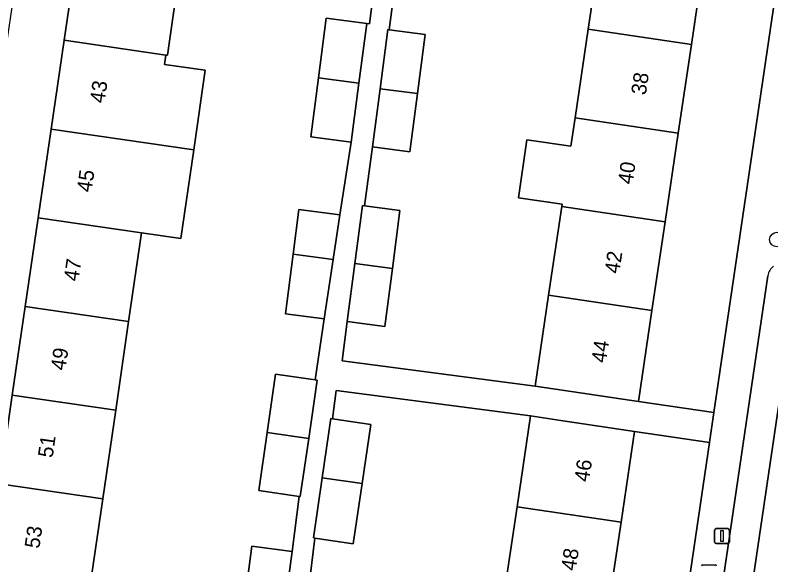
# Model space of a CAD drawing. Extents: x 163683 to 164494, y 382709 to 383872.
# Drawn here: x 163863.1 to 163913.7, y 383038.7 to 383075.5 of the extents above; entities that cross this region are included whole.
import ezdxf

# ---------------------------------------------------------------- set-up
doc = ezdxf.new("R2010")
doc.units = 0
for name, color, linetype in [('IMGEO_Boom', 7, 'Continuous'), ('IMGEO_Brandkraan', 7, 'Continuous'), ('IMGEO_Erf', 7, 'Continuous'), ('IMGEO_Lichtmast', 7, 'Continuous'), ('IMGEO_Pand', 7, 'Continuous'), ('IMGEO_Pand_nummerreeks', 7, 'Continuous'), ('IMGEO_Parkeervlak_open', 7, 'Continuous'), ('IMGEO_Rijbaan_lokaal_open', 7, 'Continuous'), ('IMGEO_Voetpad_open', 7, 'Continuous')]:
    doc.layers.add(name, color=color, linetype=linetype)

msp = doc.modelspace()

# ---------------------------------------------------------------- linework, layer by layer
at = {"layer": 'IMGEO_Boom'}
msp.add_circle((163914.106, 383060.495), 0.489, dxfattribs=at)
at = {"layer": 'IMGEO_Brandkraan'}
msp.add_line((163909.146, 383038.717), (163909.998, 383038.717), dxfattribs=at)
msp.add_lwpolyline([(163909.146, 383038.717), (163909.998, 383038.717)], dxfattribs=at)
for centre, start, end in [((163909.148, 383038.641), 91.552, 178.448), ((163909.148, 383038.641), 91.552, 178.448), ((163909.996, 383038.641), 1.552, 88.448), ((163909.996, 383038.641), 1.552, 88.448)]:
    msp.add_arc(centre, 0.0765, start, end, dxfattribs=at)
at = {"layer": 'IMGEO_Erf'}
for points in [[(163866.413, 383073.834), (163867.282, 383079.771), (163868.151, 383085.709), (163869.02, 383091.646), (163869.889, 383097.585), (163870.78, 383103.672), (163867.085, 383104.221), (163858.422, 383045.96), (163856.474, 383032.686), (163860.309, 383032.123), (163861.199, 383038.207), (163862.068, 383044.144), (163862.937, 383050.083), (163863.806, 383056.02), (163864.675, 383061.958), (163865.544, 383067.895)], [(163916.099, 383091.164), (163916.899, 383096.737), (163911.94, 383097.474), (163911.035, 383091.386), (163910.153, 383085.446), (163909.27, 383079.505), (163908.387, 383073.564), (163907.504, 383067.623), (163906.621, 383061.683), (163905.738, 383055.742), (163904.834, 383049.656), (163909.88, 383048.913)], [(163909.586, 383046.915), (163904.582, 383047.652), (163903.678, 383041.571), (163902.797, 383035.64), (163901.916, 383029.709), (163901.034, 383023.778), (163900.153, 383017.848), (163899.272, 383011.917), (163898.39, 383005.986), (163897.509, 383000.055), (163896.632, 382994.123), (163895.755, 382988.191), (163894.879, 382982.26), (163893.979, 382976.173), (163896.128, 382975.857), (163899.064, 382975.425)]]:
    msp.add_lwpolyline(points, close=True, dxfattribs=at)
for points in [[(163888.687, 383078.646), (163888.164, 383074.536), (163890.562, 383074.223), (163890.045, 383070.264), (163889.538, 383066.379), (163887.055, 383066.703), (163886.52, 383062.754), (163888.883, 383062.445), (163888.376, 383058.563), (163887.87, 383054.681), (163885.359, 383055.009), (163885.015, 383052.368), (163897.928, 383050.682), (163898.832, 383056.768), (163899.715, 383062.709), (163899.737, 383062.857), (163896.804, 383063.293), (163897.382, 383067.182), (163900.315, 383066.746), (163900.598, 383068.65), (163901.48, 383074.591), (163902.363, 383080.532)], [(163874.184, 383078.767), (163873.319, 383072.829), (163873.22, 383072.843), (163873.13, 383072.225), (163875.853, 383071.828), (163875.079, 383066.508), (163874.215, 383060.57), (163871.59, 383060.952), (163870.725, 383055.013), (163869.861, 383049.075), (163868.996, 383043.136), (163868.132, 383037.198)], [(163878.407, 383035.703), (163878.964, 383039.975), (163881.662, 383039.623), (163882.143, 383043.302), (163879.428, 383043.697), (163879.995, 383047.591), (163880.562, 383051.486), (163883.206, 383051.101), (163883.813, 383055.193), (163881.215, 383055.532), (163881.735, 383059.52), (163882.126, 383062.512), (163884.869, 383062.154), (163885.625, 383067.019), (163882.912, 383067.374), (163883.427, 383071.317), (163883.949, 383075.319), (163886.662, 383074.965), (163886.836, 383074.94), (163887.315, 383078.614)], [(163895.843, 383036.673), (163896.725, 383042.604), (163897.628, 383048.685), (163884.617, 383050.383), (163884.36, 383048.495), (163886.923, 383048.122), (163886.346, 383044.155), (163885.761, 383040.135), (163883.189, 383040.509), (163882.753, 383037.034)]]:
    msp.add_lwpolyline(points, dxfattribs=at)
at = {"layer": 'IMGEO_Lichtmast'}
for p, q in [((163909.94, 383040.249), (163909.94, 383041.049)), ((163909.94, 383041.049), (163909.94, 383040.249)), ((163910.04, 383041.149), (163910.83, 383041.149)), ((163910.83, 383041.149), (163910.04, 383041.149)), ((163910.93, 383041.049), (163910.93, 383040.249)), ((163910.93, 383040.249), (163910.93, 383041.049)), ((163910.83, 383040.149), (163910.04, 383040.149)), ((163910.04, 383040.149), (163910.83, 383040.149))]:
    msp.add_line(p, q, dxfattribs=at)
msp.add_lwpolyline([(163910.36, 383041.024), (163910.51, 383041.024), (163910.51, 383040.274), (163910.36, 383040.274), (163910.36, 383041.024)], dxfattribs=at)
for centre, start, end in [((163910.04, 383041.049), 90, 180), ((163910.04, 383041.049), 90, 180), ((163910.83, 383041.049), 0, 90), ((163910.83, 383041.049), 360, 90), ((163910.04, 383040.249), 180, 270), ((163910.04, 383040.249), 180, 270), ((163910.83, 383040.249), 270, 0), ((163910.83, 383040.249), 270, 0)]:
    msp.add_arc(centre, 0.1, start, end, dxfattribs=at)
at = {"layer": 'IMGEO_Pand'}
for points in [[(163908.387, 383073.564), (163909.27, 383079.505), (163902.363, 383080.532), (163901.48, 383074.591)], [(163874.184, 383078.767), (163867.282, 383079.771), (163866.413, 383073.834), (163873.22, 383072.843), (163873.319, 383072.829)], [(163886.662, 383074.965), (163883.949, 383075.319), (163883.427, 383071.317), (163886.139, 383070.963)], [(163888.164, 383074.536), (163888.079, 383074.547), (163887.562, 383070.588), (163890.045, 383070.264), (163890.562, 383074.223)], [(163900.598, 383068.65), (163907.504, 383067.623), (163908.387, 383073.564), (163901.48, 383074.591)], [(163873.22, 383072.843), (163866.413, 383073.834), (163865.544, 383067.895), (163875.079, 383066.508), (163875.853, 383071.828), (163873.13, 383072.225)], [(163886.139, 383070.963), (163883.427, 383071.317), (163882.912, 383067.374), (163885.625, 383067.019)], [(163890.045, 383070.264), (163887.562, 383070.588), (163887.055, 383066.703), (163889.538, 383066.379)], [(163907.504, 383067.623), (163900.598, 383068.65), (163900.315, 383066.746), (163897.382, 383067.182), (163896.804, 383063.293), (163899.737, 383062.857), (163899.715, 383062.709), (163906.621, 383061.683)], [(163871.59, 383060.952), (163874.215, 383060.57), (163875.079, 383066.508), (163865.544, 383067.895), (163864.675, 383061.958)], [(163886.52, 383062.754), (163886.372, 383062.773), (163885.865, 383058.891), (163888.376, 383058.563), (163888.883, 383062.445)], [(163905.738, 383055.742), (163906.621, 383061.683), (163899.715, 383062.709), (163898.832, 383056.768)], [(163884.869, 383062.154), (163882.126, 383062.512), (163881.735, 383059.52), (163884.416, 383059.17)], [(163871.59, 383060.952), (163864.675, 383061.958), (163863.806, 383056.02), (163870.725, 383055.013)], [(163884.416, 383059.17), (163881.735, 383059.52), (163881.215, 383055.532), (163883.813, 383055.193)], [(163888.376, 383058.563), (163885.865, 383058.891), (163885.359, 383055.009), (163887.87, 383054.681)], [(163905.738, 383055.742), (163898.832, 383056.768), (163897.928, 383050.682), (163899.889, 383050.391), (163904.834, 383049.656)], [(163869.861, 383049.075), (163870.725, 383055.013), (163863.806, 383056.02), (163862.937, 383050.083)], [(163883.206, 383051.101), (163880.562, 383051.486), (163879.995, 383047.591), (163882.779, 383047.186), (163883.345, 383051.081)], [(163862.068, 383044.144), (163868.996, 383043.136), (163869.861, 383049.075), (163862.937, 383050.083)], [(163884.36, 383048.495), (163884.255, 383048.51), (163883.677, 383044.543), (163886.346, 383044.155), (163886.923, 383048.122)], [(163896.725, 383042.604), (163903.678, 383041.571), (163904.582, 383047.652), (163899.637, 383048.387), (163897.628, 383048.685)], [(163882.779, 383047.186), (163879.995, 383047.591), (163879.428, 383043.697), (163882.143, 383043.302), (163882.212, 383043.292)], [(163886.346, 383044.155), (163883.677, 383044.543), (163883.093, 383040.523), (163883.189, 383040.509), (163885.761, 383040.135)], [(163868.132, 383037.198), (163868.996, 383043.136), (163862.068, 383044.144), (163861.199, 383038.207)], [(163902.797, 383035.64), (163903.678, 383041.571), (163896.725, 383042.604), (163895.843, 383036.673)], [(163881.099, 383035.311), (163881.662, 383039.623), (163878.964, 383039.975), (163878.407, 383035.703)]]:
    msp.add_lwpolyline(points, close=True, dxfattribs=at)
at = {"layer": 'IMGEO_Parkeervlak_open'}
for points in [[(163906.683, 382998.169), (163915.86, 383060.494)], [(163913.496, 383058.068), (163905.193, 383001.625)]]:
    msp.add_lwpolyline(points, dxfattribs=at)
msp.add_arc((163914.447, 383057.938), 0.96, 125.7792, 172.2154, dxfattribs=at)
at = {"layer": 'IMGEO_Rijbaan_lokaal_open'}
msp.add_lwpolyline([(163927.073, 383093.609), (163927.986, 383100.088), (163928.07, 383100.498), (163930.242, 383115.507), (163930.286, 383115.815), (163930.41, 383116.649), (163924.273, 383117.548), (163923.937, 383115.2), (163923.888, 383114.947), (163916.287, 383063.139), (163915.969, 383060.927), (163915.86, 383060.494), (163906.683, 382998.169), (163904.947, 382986.544), (163904.878, 382985.967)], dxfattribs=at)
at = {"layer": 'IMGEO_Voetpad_open'}
for points in [[(163920.502, 383121.853), (163917.143, 383098.439), (163916.899, 383096.737), (163916.099, 383091.164), (163909.88, 383048.913), (163909.586, 383046.915), (163899.064, 382975.425), (163896.128, 382975.857), (163895.924, 382974.275), (163892.473, 382950.83), (163894.432, 382950.591), (163894.702, 382952.384), (163894.935, 382952.595)], [(163887.315, 383078.614), (163886.836, 383074.94), (163886.662, 383074.965), (163886.139, 383070.963), (163885.625, 383067.019), (163884.869, 383062.154), (163884.416, 383059.17), (163883.813, 383055.193), (163883.206, 383051.101), (163883.345, 383051.081), (163882.779, 383047.186), (163882.212, 383043.292), (163882.143, 383043.302), (163881.662, 383039.623), (163881.099, 383035.311)], [(163882.753, 383037.034), (163883.189, 383040.509), (163883.093, 383040.523), (163883.677, 383044.543), (163884.255, 383048.51), (163884.36, 383048.495), (163884.617, 383050.383), (163897.628, 383048.685), (163899.637, 383048.387), (163904.582, 383047.652), (163909.586, 383046.915), (163909.88, 383048.913), (163904.834, 383049.656), (163899.889, 383050.391), (163897.928, 383050.682), (163885.015, 383052.368), (163885.359, 383055.009), (163885.865, 383058.891), (163886.372, 383062.773), (163886.52, 383062.754), (163887.055, 383066.703), (163887.562, 383070.588), (163888.079, 383074.547), (163888.164, 383074.536), (163888.687, 383078.646)], [(163905.193, 383001.625), (163913.496, 383058.068)]]:
    msp.add_lwpolyline(points, dxfattribs=at)
msp.add_arc((163914.447, 383057.938), 0.96, 125.7792, 172.2154, dxfattribs=at)

# ---------------------------------------------------------------- texts
at = {"layer": 'IMGEO_Pand_nummerreeks'}
for s, rotation, p in [('38', 81.5474, (163905.329, 383070.133)), ('43', 81.6751, (163869.106, 383069.586)), ('40', 81.5491, (163904.441, 383064.155)), ('45', 81.674, (163868.234, 383063.623)), ('42', 81.5474, (163903.552, 383058.172)), ('47', 81.674, (163867.361, 383057.661)), ('44', 81.5474, (163902.664, 383052.198)), ('49', 81.674, (163866.488, 383051.699)), ('51', 81.674, (163865.633, 383045.848)), ('46', 81.5476, (163901.525, 383044.23)), ('53', 81.674, (163864.743, 383039.774)), ('48', 81.5476, (163900.642, 383038.284))]:
    msp.add_text(s, height=1, rotation=rotation, dxfattribs=at).set_placement(p)

doc.saveas('drawing.dxf')
